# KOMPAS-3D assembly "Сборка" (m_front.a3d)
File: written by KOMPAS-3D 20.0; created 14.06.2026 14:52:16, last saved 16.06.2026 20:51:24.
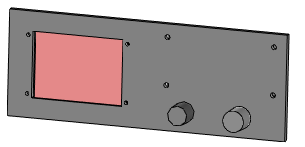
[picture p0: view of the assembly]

Document properties: Полное имя файла: D:\myProjects\Progect_esp32\box_compas\m_front.a3d

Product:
- Part/product: Сборка
    Масса: 0.984897
  - Component [detail]: Деталь  | Материал: Полипропилен  ГОСТ 26996-86 (density 900 kg/m3); Масса: 0.00646155; source file: ns4248.m3d
  - Component [detail]: Деталь  | Материал: Фторопласт-4  ГОСТ 10007-80 Е (density 2200 kg/m3); Масса: 0.00961888; source file: TZT_EC11.m3d
  - Component [detail]: Деталь  | Масса: 0.43011; source file: front.m3d
  - Component [detail]: Деталь  | Масса: 0.324771; source file: ups.m3d
  - Component [detail]: Деталь  | Масса: 0.213936; source file: chip.m3d

Referenced files in D:\myProjects\Progect_esp32\box_compas\: front.m3d, ups.m3d, chip.m3d, TZT_EC11.m3d, ns4248.m3d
